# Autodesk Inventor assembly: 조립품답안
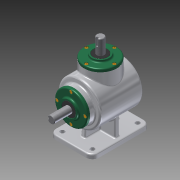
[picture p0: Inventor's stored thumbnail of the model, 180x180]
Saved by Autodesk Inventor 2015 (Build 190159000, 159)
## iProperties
Created: 2016-09
Part Number: 조립품답안
Document SubType Name: Assembly
Designer: LineLG02
Author: LineLG02
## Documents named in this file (14)
- C:\Users\LineLG02\Desktop\460907V1018\조립품답안.iam
- C:\Users\LineLG02\Desktop\460907V1018\본체.ipt
- C:\Users\LineLG02\Desktop\460907V1018\커버.ipt
- C:\Users\LineLG02\Desktop\460907V1018\베어링 6203.ipt
- C:\Users\LineLG02\Desktop\460907V1018\오일실 17 32 8.ipt
- C:\Users\LineLG02\Desktop\460907V1018\메인 축.ipt
- 메인 축.ipt
- C:\Users\LineLG02\Desktop\460907V1018\키 5x5.ipt
- C:\Users\LineLG02\Desktop\460907V1018\서브 축.ipt
- 서브 축.ipt
- C:\Users\LineLG02\Desktop\460907V1018\키 4x4.ipt
- C:\Users\LineLG02\Desktop\460907V1018\메인 베벨기어.ipt
- C:\Users\LineLG02\Desktop\460907V1018\서브 베벨기어.ipt
- C:\Users\LineLG02\Desktop\460907V1018\M4.ipt
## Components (8 placed, 1 different names)
1. M4:2 — 각도:4
2. M4:3
3. M4:4
4. M4:5
5. M4:1 — 각도:3
6. M4:6
7. M4:7
8. M4:8
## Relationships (2: Angle 2)
- 각도:3 [Angle]: M4:1
- 각도:4 [Angle]: M4:2
